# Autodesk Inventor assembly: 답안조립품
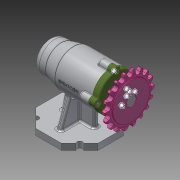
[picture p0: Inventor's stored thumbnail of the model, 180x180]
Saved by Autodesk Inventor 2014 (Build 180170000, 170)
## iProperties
Created: 2021-01
Part Number: 답안조립품
Document SubType Name: Assembly
Designer: kh
Author: kh
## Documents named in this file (12)
- C:\Users\kh\Desktop\710106V1015\답안조립품.iam
- C:\Users\kh\Desktop\710106V1015\본체.ipt
- C:\Users\kh\Desktop\710106V1015\멈춤나사 M3.ipt
- C:\Users\kh\Desktop\710106V1015\베어링 6004.ipt
- C:\Users\kh\Desktop\710106V1015\베어링 51202.ipt
- C:\Users\kh\Desktop\710106V1015\볼트 M4.ipt
- C:\Users\kh\Desktop\710106V1015\스프로킷.ipt
- C:\Users\kh\Desktop\710106V1015\어댑터슬리브.ipt
- C:\Users\kh\Desktop\710106V1015\오일 실.ipt
- C:\Users\kh\Desktop\710106V1015\축.ipt
- C:\Users\kh\Desktop\710106V1015\커버.ipt
- C:\Users\kh\Desktop\710106V1015\키 5 x 5 x 14.ipt
